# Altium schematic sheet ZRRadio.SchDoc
size A4
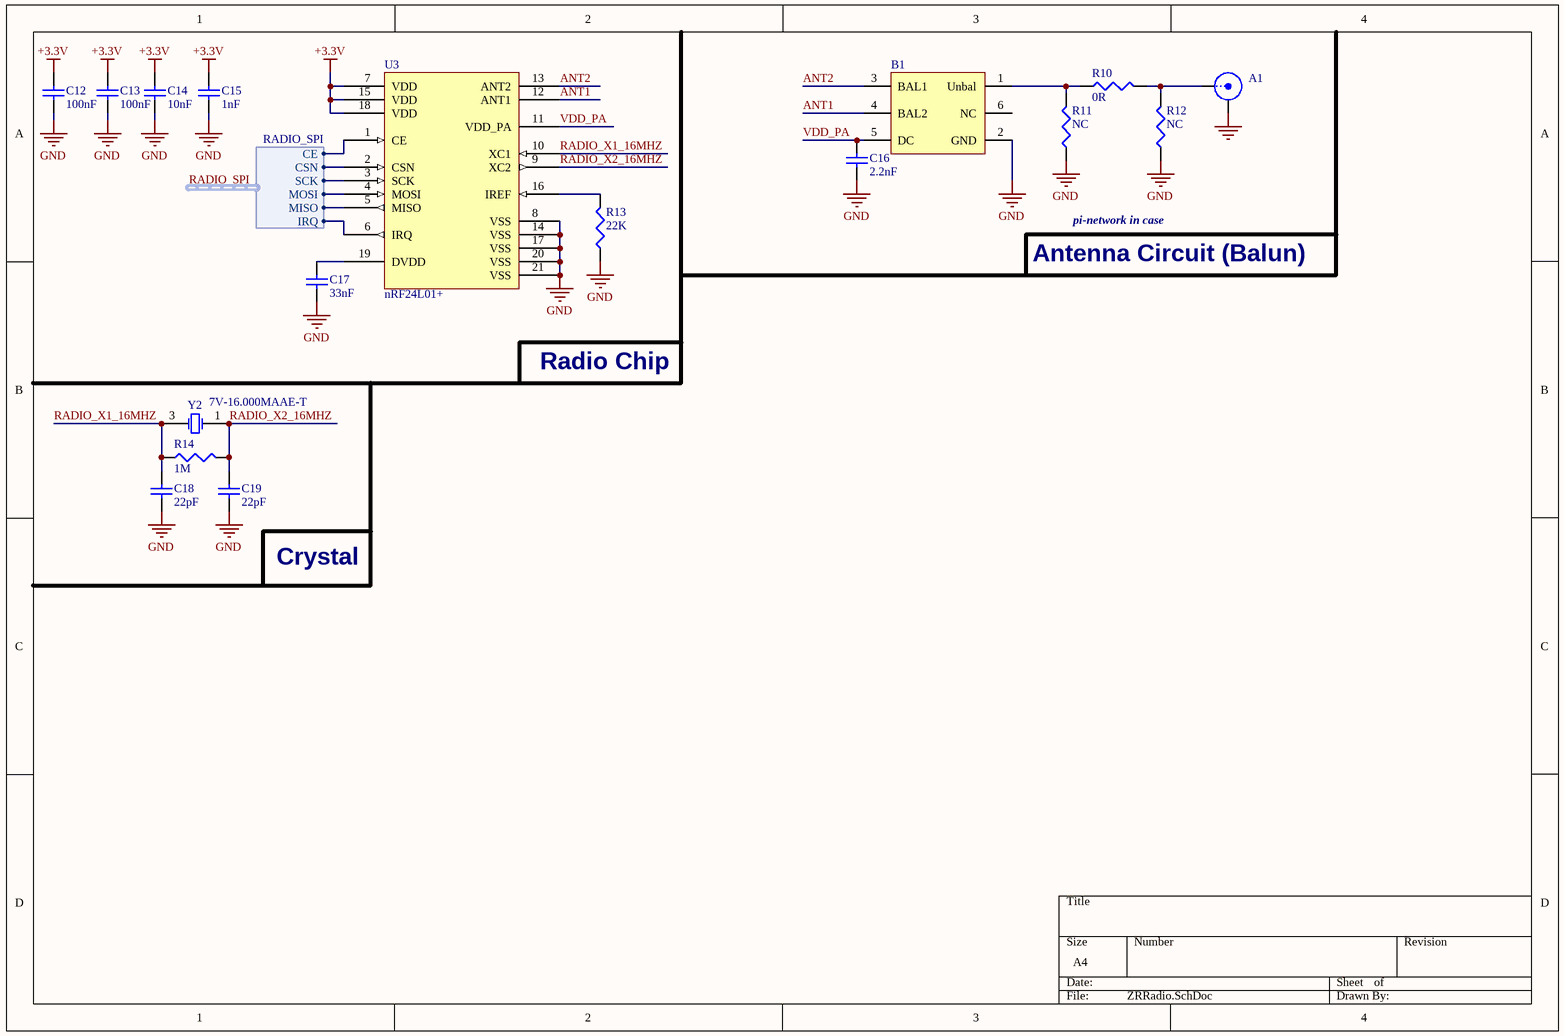
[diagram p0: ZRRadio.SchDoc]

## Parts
A1  142-4701-801  [142-4701-801]  (value not drawn)
B1  2450BM14A0002T  [2450BM14A0002]  (value not drawn)
C12  100nF  [0402]
C13  100nF  [0402]
C14  10nF  [0402]
C15  1nF  [0402]
C16  2.2nF  [0402]
C17  33nF  [0402]
C18  22pF  [0402]
C19  22pF  [0402]
R10  0R  [0402]
R11  value NC  [0402 - NOBODY]  (hidden comment: 0402-NC)
R12  value NC  [0402 - NOBODY]  (hidden comment: 0402-NC)
R13  value 22K  [0402]  (hidden comment: 22K 0402 1/16W ±1%)
R14  1M  [0402]
U3  nRF24L01+  [QFN50P400X400X95_HS-21L]
Y2  7V-16.000MAAE-T  [3.2x2.5 CRYSTAL]

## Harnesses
RADIO_SPI: MOSI, MISO, SCK, CSN, CE, IRQ

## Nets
+3.3V: C12.2 C13.2 C14.2 C15.2 U3.7(VDD) U3.15(VDD) U3.18(VDD)
GND: A1.2(Y) B1.2(GND) C12.1 C13.1 C14.1 C15.1 C16.1 C17.1 C18.1 C19.1 R11.1 R12.1 R13.1 U3.8(VSS) U3.14(VSS) U3.17(VSS) U3.20(VSS) U3.21(VSS) Y2.2(GND) Y2.4(GND)
ANT1: B1.4(BAL2) U3.12(ANT1)
ANT2: B1.3(BAL1) U3.13(ANT2)
RADIO_SPI.CE: U3.1(CE) ; harness RADIO_SPI.CE
RADIO_SPI.CSN: U3.2(CSN) ; harness RADIO_SPI.CSN
RADIO_SPI.IRQ: U3.6(IRQ) ; harness RADIO_SPI.IRQ
RADIO_SPI.MISO: U3.5(MISO) ; harness RADIO_SPI.MISO
RADIO_SPI.MOSI: U3.4(MOSI) ; harness RADIO_SPI.MOSI
RADIO_SPI.SCK: U3.3(SCK) ; harness RADIO_SPI.SCK
RADIO_X1_16MHZ: C18.2 R14.1 U3.10(XC1) Y2.3(X2)
RADIO_X2_16MHZ: C19.2 R14.2 U3.9(XC2) Y2.1(X1)
VDD_PA: B1.5(DC) C16.2 U3.11(VDD_PA)
NetA1_1: A1.1(X) R10.2 R12.2
NetB1_1: B1.1(Unbal) R10.1 R11.2
NetC17_2: C17.2 U3.19(DVDD)
NetR13_2: R13.2 U3.16(IREF)

Not connected (* = marked no-connect by the designer): B1 6(NC)

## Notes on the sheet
- pi-network in case
- Antenna Circuit (Balun)
- Radio Chip
- Crystal

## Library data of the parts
A1 = 142-4701-801: JOHNSON  142-4701-801  SMA FEMELLE REVERSE POLARITY TERMINAISON
B1 = 2450BM14A0002T: Johanson Technology Impedance Matched Balun Filter Integrated Passive for nRF24L01
C12 C13 = 100nF: 100nF 0402 X7R 16V ±10%
C14 = 10nF: 10nF 0402 X7R 25V ±5%
C15 = 1nF: 1nF 0402 X7R 50V ±10%
C16 = 2.2nF: 2.2nF 0402 X7R 50V ±10%
C17 = 33nF: 33nF 0402 X7R 50V ±10%
C18 C19 = 22pF: 22pF 0402 NP0/CG0 50V ±5%
R10 = 0R: 0R 0402 1/16W ±0.05R
R11 R12 = 0402-NC: NOT CONNECTED
R13 = 22K
R14 = 1M: 1M 0402 1/16W ±1%
U3 = nRF24L01+: Nordic Semi Ultra low power 2.4GHz RF Transceiver IC
Y2 = 7V-16.000MAAE-T: TXC - 7V-16.000MAAE-T, 16MHZ, 30PPM, 12PF - CRYSTAL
